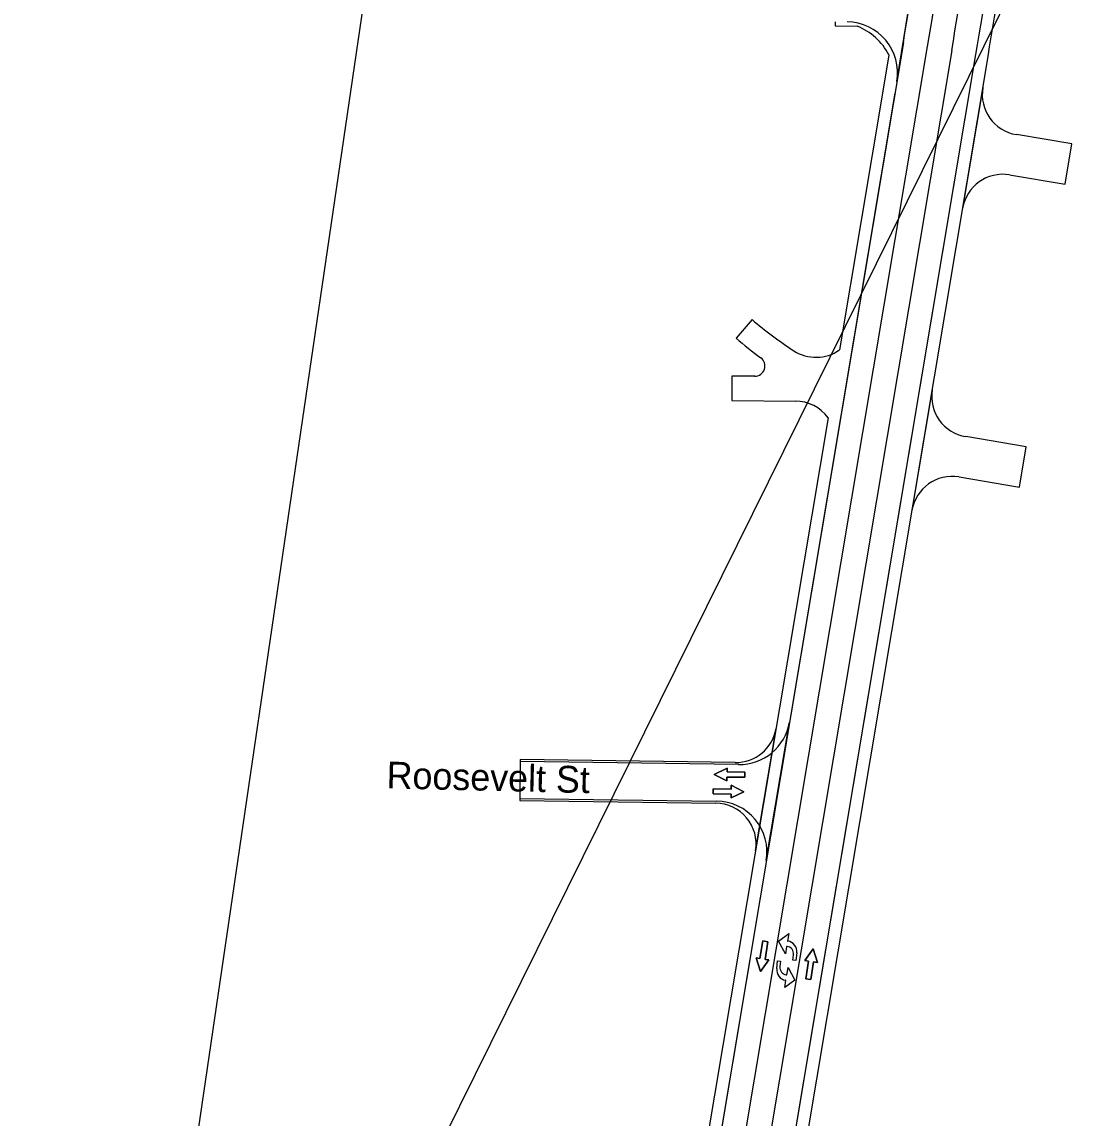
# Model space of a CAD drawing. Extents: x 14104283 to 14120882, y 8635219 to 8671666.
# Drawn here: x 14118757 to 14119277, y 8669626 to 8670163 of the extents above; entities that cross this region are included whole.
import ezdxf

# ---------------------------------------------------------------- set-up
doc = ezdxf.new("R2010")
doc.units = 0
for name, color, linetype in [('Cell', 7, 'Continuous'), ('dsnNonPlotable', 7, 'Continuous'), ('dsnPaintExistingEdgeLineRightWhite', 7, 'Continuous'), ('dsnPaintExistingNoPassingYellow', 7, 'Continuous'), ('dsnShadingPaved', 7, 'Continuous'), ('dsnStgShadingPrevPav', 7, 'Continuous'), ('dsnTextFinalPlan', 7, 'Continuous'), ('Level 2', 7, 'Continuous'), ('Level 5', 7, 'Continuous')]:
    doc.layers.add(name, color=color, linetype=linetype)

msp = doc.modelspace()

# ---------------------------------------------------------------- linework, layer by layer
at = {"layer": 'Cell'}
for p, q in [((14119131.92, 8669712.89), (14119132.11, 8669712.87)), ((14119131.82, 8669710.26), (14119131.51, 8669710.3)), ((14119131.3, 8669696.36), (14119131.61, 8669696.32)), ((14119131.19, 8669693.72), (14119131.01, 8669693.74))]:
    msp.add_line(p, q, dxfattribs=at)
for points in [[(14119127.59, 8669712.84), (14119132.51, 8669716.53), (14119131.92, 8669712.89)], [(14119127.59, 8669712.84), (14119132.51, 8669716.53), (14119131.92, 8669712.89)], [(14119131.51, 8669710.3), (14119130.92, 8669706.66), (14119127.59, 8669712.84)], [(14119131.51, 8669710.3), (14119130.92, 8669706.66), (14119127.59, 8669712.84)], [(14119131.92, 8669712.89), (14119132.11, 8669712.87)], [(14119131.82, 8669710.26), (14119131.51, 8669710.3)], [(14119136.48, 8669707.1), (14119136.07, 8669703.44), (14119134.59, 8669703.61), (14119134.88, 8669706.22)], [(14119136.48, 8669707.1), (14119136.07, 8669703.44), (14119134.59, 8669703.61), (14119134.88, 8669706.22)], [(14119126.64, 8669699.51), (14119127.04, 8669703.17), (14119128.52, 8669703.01), (14119128.24, 8669700.4)], [(14119126.64, 8669699.51), (14119127.04, 8669703.17), (14119128.52, 8669703.01), (14119128.24, 8669700.4)], [(14119131.3, 8669696.36), (14119131.61, 8669696.32)], [(14119131.61, 8669696.32), (14119132.2, 8669699.96), (14119135.52, 8669693.77)], [(14119131.61, 8669696.32), (14119132.2, 8669699.96), (14119135.52, 8669693.77)], [(14119135.52, 8669693.77), (14119130.6, 8669690.09), (14119131.19, 8669693.72)], [(14119135.52, 8669693.77), (14119130.6, 8669690.09), (14119131.19, 8669693.72)], [(14119131.19, 8669693.72), (14119131.01, 8669693.74)]]:
    msp.add_lwpolyline(points, dxfattribs=at)
for centre, major_axis in [((14119131.53, 8669707.65), (-0.58, -5.22)), ((14119131.53, 8669707.65), (-0.58, -5.22)), ((14119131.41, 8669706.6), (-0.4, -3.66)), ((14119131.41, 8669706.6), (-0.4, -3.66)), ((14119131.59, 8669698.97), (0.58, 5.22)), ((14119131.59, 8669698.97), (0.58, 5.22)), ((14119131.7, 8669700.01), (0.4, 3.66)), ((14119131.7, 8669700.01), (0.4, 3.66))]:
    msp.add_ellipse(centre, major_axis=major_axis, ratio=0.9474, start_param=1.570796, end_param=3.141593, dxfattribs=at)
at = {"layer": 'dsnNonPlotable'}
for points in [[(14118774.15, 8669147.84), (14119001.66, 8670698.74), (14119501.31, 8670625.45), (14119273.81, 8669074.54)], [(14118631.64, 8668945.1), (14119326.37, 8670350.23), (14120231.75, 8669902.59), (14119537.02, 8668497.46)]]:
    msp.add_lwpolyline(points, close=True, dxfattribs=at)
at = {"layer": 'dsnPaintExistingEdgeLineRightWhite'}
msp.add_line((14119184.51, 8670128.17), (14119019.22, 8669141.32), dxfattribs=at)
msp.add_line((14119184.51, 8670128.17), (14119019.22, 8669141.32), dxfattribs=at)
msp.add_lwpolyline([(14119029.87, 8669002.67), (14119054.72, 8669135.38), (14119224.18, 8670147.05)], dxfattribs=at)
msp.add_lwpolyline([(14119029.87, 8669002.67), (14119054.72, 8669135.38), (14119224.18, 8670147.05)], dxfattribs=at)
msp.add_arc((14116247.64, 8670645.61), 3018, 350.49147, 353.44431, dxfattribs=at)
at = {"layer": 'dsnPaintExistingNoPassingYellow'}
for p, q in [((14119031.05, 8669139.34), (14119200.51, 8670151.01)), ((14119212.34, 8670149.03), (14119042.89, 8669137.36))]:
    msp.add_line(p, q, dxfattribs=at)
for radius in [2994, 3006]:
    msp.add_arc((14116247.64, 8670645.61), radius, 350.49147, 353.44431, dxfattribs=at)
at = {"layer": 'dsnShadingPaved'}
for p, q in [((14119185.47, 8670133.9), (14119196.49, 8670202.17)), ((14119188.66, 8670152.92), (14119019.21, 8669141.25)), ((14119031.04, 8669139.27), (14119200.49, 8670150.94)), ((14119031.05, 8669139.34), (14119200.51, 8670151.01)), ((14119212.34, 8670149.03), (14119042.89, 8669137.36)), ((14119212.34, 8670149.03), (14119042.89, 8669137.36)), ((14119054.72, 8669135.38), (14119224.18, 8670147.05)), ((14119121.56, 8669752.31), (14119132.92, 8669820.16)), ((14119001.1, 8669800.75), (14119000.85, 8669782.76)), ((14119107.92, 8669799.29), (14119001.1, 8669800.75)), ((14119000.85, 8669782.76), (14119097.24, 8669781.44))]:
    msp.add_line(p, q, dxfattribs=at)
for centre, radius, start, end in [((14116247.63, 8670645.53), 2982, 350.49147, 353.44431), ((14116247.63, 8670645.53), 2994, 350.49147, 353.44431), ((14116247.64, 8670645.61), 2994, 350.49147, 353.44431), ((14116247.64, 8670645.61), 3006, 350.49147, 353.44431), ((14116247.64, 8670645.61), 3006, 350.49147, 353.44431), ((14116247.64, 8670645.61), 3018, 350.49147, 353.44431), ((14119160.81, 8670138.03), 25, 350.4915, 89.2381), ((14119108.27, 8669824.29), 25, 269.2165, 350.4915), ((14119096.9, 8669756.44), 25, 350.4915, 89.2165)]:
    msp.add_arc(centre, radius, start, end, dxfattribs=at)
at = {"layer": 'dsnStgShadingPrevPav'}
for p, q in [((14119155.32, 8670163.1), (14119155.29, 8670161.1)), ((14119155.29, 8670161.1), (14119166.06, 8670160.96)), ((14119060.64, 8669134.39), (14119230.09, 8670146.06)), ((14119181.56, 8670146.9), (14119178.59, 8670129.16)), ((14119227.55, 8670130.88), (14119217.64, 8670071.7)), ((14119178.59, 8670129.16), (14119157.36, 8670002.37)), ((14119271.21, 8670103.29), (14119243.97, 8670107.85)), ((14119267.91, 8670083.56), (14119271.21, 8670103.29)), ((14119240.67, 8670088.13), (14119267.91, 8670083.56)), ((14119114.56, 8670017.23), (14119106.77, 8670008.1)), ((14119104.75, 8669989.61), (14119104.64, 8669977.61)), ((14119115.86, 8669989.52), (14119104.75, 8669989.61)), ((14119202.77, 8669982.94), (14119192.86, 8669923.76)), ((14119104.64, 8669977.61), (14119135.8, 8669977.34)), ((14119151.79, 8669969.11), (14119013.3, 8669142.32)), ((14119248.78, 8669954.96), (14119219.19, 8669959.91)), ((14119245.48, 8669935.23), (14119248.78, 8669954.96)), ((14119215.99, 8669940.17), (14119245.48, 8669935.23)), ((14119116.28, 8669757.14), (14119126.31, 8669817.01)), ((14119001.11, 8669801.75), (14119000.84, 8669781.76)), ((14119106.31, 8669800.32), (14119001.11, 8669801.75)), ((14119000.84, 8669781.76), (14119096.83, 8669780.44))]:
    msp.add_line(p, q, dxfattribs=at)
for centre, radius, start, end in [((14116247.64, 8670645.61), 3024, 350.49147, 353.44431), ((14119154.92, 8670133.11), 30, 27.3614, 68.1986), ((14119247.28, 8670127.58), 20, 170.4915, 260.4915), ((14119237.36, 8670068.4), 20, 80.4915, 170.4915), ((14119240.4, 8670164.87), 194, 229.5568, 237.1074), ((14119240.4, 8670164.87), 206, 229.5568, 233.8406), ((14119145.91, 8670018.77), 20, 237.1074, 304.9185), ((14119115.9, 8669994.52), 5, 269.4915, 53.8406), ((14119222.5, 8669979.64), 20, 170.4915, 260.4915), ((14119135.62, 8669957.34), 20, 36.0645, 89.4915), ((14119212.58, 8669920.46), 20, 80.4915, 170.4915), ((14119106.58, 8669820.31), 20, 269.2165, 350.4915), ((14119096.56, 8669760.45), 20, 350.4915, 89.2165)]:
    msp.add_arc(centre, radius, start, end, dxfattribs=at)
at = {"layer": 'Level 2'}
for points in [[(14119111.06, 8669793.09), (14119111.09, 8669795.59), (14119102.34, 8669795.69), (14119102.36, 8669797.56), (14119096.07, 8669794.51), (14119102.29, 8669791.31), (14119102.31, 8669793.19)], [(14119095.6, 8669787.44), (14119095.57, 8669784.94), (14119104.32, 8669784.85), (14119104.3, 8669782.97), (14119110.58, 8669786.03), (14119104.37, 8669789.22), (14119104.35, 8669787.35)], [(14119122.29, 8669712.56), (14119119.82, 8669712.95), (14119118.46, 8669704.31), (14119116.61, 8669704.6), (14119118.72, 8669697.94), (14119122.78, 8669703.63), (14119120.93, 8669703.92)], [(14119140.89, 8669694.46), (14119143.36, 8669694.07), (14119144.72, 8669702.72), (14119146.57, 8669702.42), (14119144.46, 8669709.08), (14119140.4, 8669703.4), (14119142.25, 8669703.11)]]:
    msp.add_lwpolyline(points, close=True, dxfattribs=at)
at = {"layer": 'Level 5'}
for points in [[(14119102.31, 8669793.19), (14119102.29, 8669791.31), (14119096.07, 8669794.51), (14119102.36, 8669797.56), (14119102.34, 8669795.69), (14119111.09, 8669795.59), (14119111.06, 8669793.09), (14119102.31, 8669793.19)], [(14119104.35, 8669787.35), (14119104.37, 8669789.22), (14119110.58, 8669786.03), (14119104.3, 8669782.97), (14119104.32, 8669784.85), (14119095.57, 8669784.94), (14119095.6, 8669787.44), (14119104.35, 8669787.35)], [(14119120.93, 8669703.92), (14119122.78, 8669703.63), (14119118.72, 8669697.94), (14119116.61, 8669704.6), (14119118.46, 8669704.31), (14119119.82, 8669712.95), (14119122.29, 8669712.56), (14119120.93, 8669703.92)], [(14119142.25, 8669703.11), (14119140.4, 8669703.4), (14119144.46, 8669709.08), (14119146.57, 8669702.42), (14119144.72, 8669702.72), (14119143.36, 8669694.07), (14119140.89, 8669694.46), (14119142.25, 8669703.11)]]:
    msp.add_lwpolyline(points, dxfattribs=at)

# ---------------------------------------------------------------- texts
at = {"layer": 'dsnTextFinalPlan'}
msp.add_text('Roosevelt St', height=13.125, rotation=358.6374, dxfattribs=at).set_placement((14118935.54, 8669787.68))

doc.saveas('drawing.dxf')
